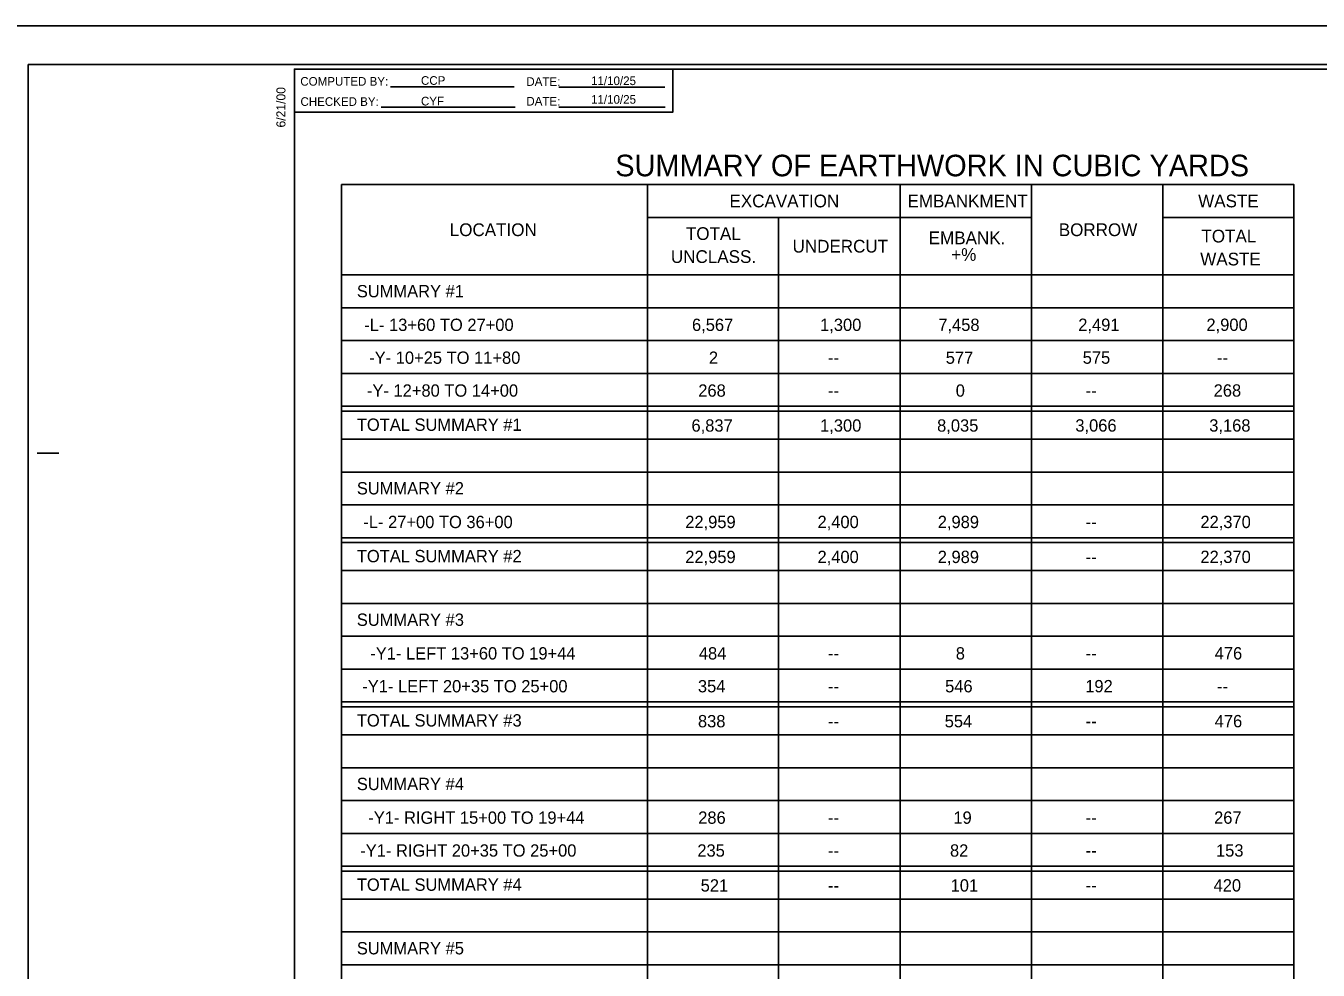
# Model space of a CAD drawing. Extents: x 970719 to 972233, y 692255 to 693335.
# Drawn here: x 971224.1 to 971523.3, y 693116.3 to 693335 of the extents above; entities that cross this region are included whole.
import ezdxf

# ---------------------------------------------------------------- set-up
doc = ezdxf.new("R2010")
doc.units = 0
for name, color, linetype in [('Exist Horizontal Alignment', 7, 'Continuous'), ('Old_Level_1', 7, 'Continuous'), ('Old_Level_2', 7, 'Continuous'), ('Prop EOT', 7, 'Continuous'), ('Prop Horizontal Alignment Direction Label', 7, 'Continuous'), ('Prop Horizontal Alignment Tick Label', 7, 'Continuous')]:
    doc.layers.add(name, color=color, linetype=linetype)

msp = doc.modelspace()

# ---------------------------------------------------------------- linework, layer by layer
at = {"layer": 'Exist Horizontal Alignment'}
for p, q in [((971308.55, 693320.82), (971337.17, 693320.82)), ((971347.49, 693320.76), (971372.05, 693320.76)), ((971306.37, 693316.14), (971337.45, 693316.14)), ((971347.55, 693316.16), (971372.11, 693316.16)), ((971226.73, 693235.98), (971231.73, 693235.98))]:
    msp.add_line(p, q, dxfattribs=at)
for points in [[(971886.29, 693324.98), (971286.29, 693324.98), (971286.29, 692904.98), (971886.29, 692904.98)], [(971286.29, 693324.98), (971373.89, 693324.98), (971373.89, 693314.98), (971286.29, 693314.98)]]:
    msp.add_lwpolyline(points, close=True, dxfattribs=at)
at = {"layer": 'Old_Level_1'}
msp.add_lwpolyline([(971893.09, 693334.98), (971219.49, 693334.98), (971219.49, 692894.98), (971893.09, 692894.98)], close=True, dxfattribs=at)
at = {"layer": 'Prop EOT'}
msp.add_lwpolyline([(971891.29, 693326), (971224.69, 693326), (971224.69, 692903.96), (971891.29, 692903.96)], close=True, dxfattribs=at)
at = {"layer": 'Prop Horizontal Alignment Direction Label'}
msp.add_line((971893.09, 693334.98), (971219.49, 693334.98), dxfattribs=at)
at = {"layer": 'Prop Horizontal Alignment Tick Label'}
for p, q in [((971297.21, 693010.98), (971297.21, 693298.22)), ((971368.03, 693298.22), (971297.21, 693298.22)), ((971368.03, 693010.98), (971368.03, 693290.61)), ((971368.03, 693290.61), (971408.08, 693290.61)), ((971398.41, 693010.98), (971398.41, 693290.61)), ((971426.58, 693010.98), (971426.58, 693290.61)), ((971426.58, 693269.68), (971426.58, 693290.61)), ((971456.97, 693010.98), (971456.97, 693290.61)), ((971487.35, 693010.98), (971487.35, 693290.61)), ((971517.73, 693010.98), (971517.73, 693290.61)), ((971517.73, 693277.29), (971297.21, 693277.29)), ((971297.21, 693269.68), (971426.58, 693269.68)), ((971297.21, 693269.68), (971426.58, 693269.68)), ((971426.58, 693010.98), (971426.58, 693269.68)), ((971426.58, 693269.68), (971517.73, 693269.68)), ((971426.58, 693262.08), (971297.21, 693262.08)), ((971426.58, 693262.08), (971297.21, 693262.08)), ((971517.73, 693262.08), (971426.58, 693262.08)), ((971517.73, 693262.08), (971426.58, 693262.08)), ((971297.21, 693254.47), (971426.58, 693254.47)), ((971426.58, 693254.47), (971517.73, 693254.47)), ((971297.21, 693246.86), (971426.58, 693246.86)), ((971297.21, 693246.86), (971426.58, 693246.86)), ((971426.58, 693246.86), (971297.21, 693246.86)), ((971426.58, 693246.86), (971297.21, 693246.86)), ((971297.21, 693245.75), (971426.58, 693245.75)), ((971517.73, 693246.86), (971426.58, 693246.86)), ((971517.73, 693246.86), (971426.58, 693246.86)), ((971426.58, 693246.86), (971517.73, 693246.86)), ((971426.58, 693246.86), (971517.73, 693246.86)), ((971426.58, 693245.75), (971517.73, 693245.75)), ((971426.58, 693239.25), (971297.21, 693239.25)), ((971517.73, 693239.25), (971426.58, 693239.25)), ((971297.21, 693231.64), (971426.58, 693231.64)), ((971297.21, 693231.64), (971426.58, 693231.64)), ((971426.58, 693231.64), (971517.73, 693231.64)), ((971426.58, 693231.64), (971517.73, 693231.64)), ((971426.58, 693224.03), (971297.21, 693224.03)), ((971426.58, 693224.03), (971297.21, 693224.03)), ((971517.73, 693224.03), (971426.58, 693224.03)), ((971517.73, 693224.03), (971426.58, 693224.03)), ((971297.21, 693216.42), (971426.58, 693216.42)), ((971297.21, 693216.42), (971426.58, 693216.42)), ((971297.21, 693215.32), (971426.58, 693215.32)), ((971426.58, 693216.42), (971517.73, 693216.42)), ((971426.58, 693216.42), (971517.73, 693216.42)), ((971426.58, 693215.32), (971517.73, 693215.32)), ((971426.58, 693208.81), (971297.21, 693208.81)), ((971426.58, 693208.81), (971297.21, 693208.81)), ((971517.73, 693208.81), (971426.58, 693208.81)), ((971517.73, 693208.81), (971426.58, 693208.81)), ((971297.21, 693201.2), (971426.58, 693201.2)), ((971297.21, 693201.2), (971426.58, 693201.2)), ((971426.58, 693201.2), (971517.73, 693201.2)), ((971426.58, 693201.2), (971517.73, 693201.2)), ((971426.58, 693193.59), (971297.21, 693193.59)), ((971426.58, 693193.59), (971297.21, 693193.59)), ((971517.73, 693193.59), (971426.58, 693193.59)), ((971517.73, 693193.59), (971426.58, 693193.59)), ((971426.58, 693185.99), (971297.21, 693185.99)), ((971426.58, 693185.99), (971297.21, 693185.99)), ((971517.73, 693185.99), (971426.58, 693185.99)), ((971517.73, 693185.99), (971426.58, 693185.99)), ((971297.21, 693178.38), (971426.58, 693178.38)), ((971297.21, 693178.38), (971426.58, 693178.38)), ((971297.21, 693177.27), (971426.58, 693177.27)), ((971426.58, 693178.38), (971517.73, 693178.38)), ((971426.58, 693178.38), (971517.73, 693178.38)), ((971426.58, 693177.27), (971517.73, 693177.27)), ((971426.58, 693170.77), (971297.21, 693170.77)), ((971426.58, 693170.77), (971297.21, 693170.77)), ((971517.73, 693170.77), (971426.58, 693170.77)), ((971517.73, 693170.77), (971426.58, 693170.77)), ((971297.21, 693163.16), (971426.58, 693163.16)), ((971297.21, 693163.16), (971426.58, 693163.16)), ((971426.58, 693163.16), (971517.73, 693163.16)), ((971426.58, 693163.16), (971517.73, 693163.16)), ((971426.58, 693155.55), (971297.21, 693155.55)), ((971426.58, 693155.55), (971297.21, 693155.55)), ((971517.73, 693155.55), (971426.58, 693155.55)), ((971517.73, 693155.55), (971426.58, 693155.55)), ((971426.58, 693147.94), (971297.21, 693147.94)), ((971426.58, 693147.94), (971297.21, 693147.94)), ((971517.73, 693147.94), (971426.58, 693147.94)), ((971517.73, 693147.94), (971426.58, 693147.94)), ((971297.21, 693140.33), (971426.58, 693140.33)), ((971297.21, 693140.33), (971426.58, 693140.33)), ((971297.21, 693139.23), (971426.58, 693139.23)), ((971426.58, 693140.33), (971517.73, 693140.33)), ((971426.58, 693140.33), (971517.73, 693140.33)), ((971426.58, 693139.23), (971517.73, 693139.23)), ((971426.58, 693132.72), (971297.21, 693132.72)), ((971426.58, 693132.72), (971297.21, 693132.72)), ((971517.73, 693132.72), (971426.58, 693132.72)), ((971517.73, 693132.72), (971426.58, 693132.72)), ((971297.21, 693125.11), (971426.58, 693125.11)), ((971297.21, 693125.11), (971426.58, 693125.11)), ((971426.58, 693125.11), (971517.73, 693125.11)), ((971426.58, 693125.11), (971517.73, 693125.11)), ((971426.58, 693117.5), (971297.21, 693117.5)), ((971426.58, 693117.5), (971297.21, 693117.5)), ((971517.73, 693117.5), (971426.58, 693117.5)), ((971517.73, 693117.5), (971426.58, 693117.5))]:
    msp.add_line(p, q, dxfattribs=at)
for points in [[(971426.58, 693298.22), (971368.03, 693298.22), (971368.03, 693290.61), (971426.58, 693290.61)], [(971456.97, 693298.22), (971426.58, 693298.22), (971426.58, 693290.61), (971456.97, 693290.61)], [(971456.97, 693298.22), (971487.35, 693298.22), (971487.35, 693277.29), (971456.97, 693277.29)], [(971487.35, 693298.22), (971517.73, 693298.22), (971517.73, 693290.61), (971487.35, 693290.61)]]:
    msp.add_lwpolyline(points, close=True, dxfattribs=at)

# ---------------------------------------------------------------- texts
at = {"layer": 'Exist Horizontal Alignment'}
for s, height, p in [('COMPUTED BY:', 1.9999, (971287.67, 693321.12)), ('DATE:', 2, (971340.01, 693321.08)), ('CHECKED BY:', 1.9999, (971287.71, 693316.44)), ('DATE:', 2, (971340.01, 693316.52)), ('SUMMARY OF EARTHWORK IN CUBIC YARDS', 5, (971360.6, 693300.13))]:
    msp.add_text(s, height=height, dxfattribs=at).set_placement(p)
msp.add_text('6/21/00', height=2.1, rotation=90, dxfattribs=at).set_placement((971284.23, 693311.43))
at = {"layer": 'Old_Level_2'}
for s, p in [('CCP', (971315.61, 693321.32)), ('11/10/25', (971354.99, 693321.26)), ('CYF', (971315.61, 693316.54)), ('11/10/25', (971354.99, 693316.94))]:
    msp.add_text(s, height=2, dxfattribs=at).set_placement(p)
at = {"layer": 'Prop Horizontal Alignment Tick Label'}
for s, p in [('EXCAVATION', (971387.04, 693292.94)), ('EMBANKMENT', (971428.26, 693292.94)), ('WASTE', (971495.55, 693292.94)), ('LOCATION', (971322.27, 693286.28)), ('TOTAL', (971376.95, 693285.39)), ('EMBANK.', (971433.16, 693284.4)), ('BORROW', (971463.28, 693286.28)), ('TOTAL', (971496.31, 693284.81)), ('UNDERCUT', (971401.64, 693282.47)), ('UNCLASS.', (971373.48, 693280.06)), ('+%', (971438.38, 693280.54)), ('WASTE', (971496.03, 693279.49))]:
    msp.add_text(s, height=2.948, rotation=360, dxfattribs=at).set_placement(p)
for s, height, p in [('SUMMARY #1', 2.853, (971300.76, 693272.1)), ('-L- 13+60 TO 27+00', 2.8534, (971302.49, 693264.31)), ('6,567', 2.853, (971378.36, 693264.31)), ('1,300', 2.853, (971408.02, 693264.31)), ('7,458', 2.853, (971435.39, 693264.31)), ('2,491', 2.853, (971467.79, 693264.32)), ('2,900', 2.853, (971497.47, 693264.32)), ('-Y- 10+25 TO 11+80', 2.8534, (971303.62, 693256.7)), ('2', 2.85, (971382.27, 693256.7)), ('--', 2.853, (971409.85, 693256.7)), ('577', 2.853, (971437.11, 693256.7)), ('575', 2.853, (971468.82, 693256.71)), ('--', 2.853, (971499.9, 693256.71)), ('-Y- 12+80 TO 14+00', 2.8534, (971303.1, 693249.09)), ('268', 2.853, (971379.81, 693249.09)), ('0', 2.85, (971439.42, 693249.09)), ('268', 2.853, (971499.14, 693249.1)), ('--', 2.853, (971409.85, 693249.09)), ('--', 2.853, (971469.51, 693249.1)), ('TOTAL SUMMARY #1', 2.8534, (971300.76, 693241.18)), ('6,837', 2.853, (971378.24, 693240.99)), ('1,300', 2.853, (971408.02, 693240.99)), ('8,035', 2.853, (971435.11, 693240.99)), ('3,066', 2.853, (971467.11, 693241)), ('3,168', 2.853, (971498.12, 693241)), ('SUMMARY #2', 2.853, (971300.76, 693226.45)), ('-L- 27+00 TO 36+00', 2.8534, (971302.27, 693218.65)), ('22,959', 2.853, (971376.8, 693218.65)), ('2,400', 2.853, (971407.42, 693218.65)), ('2,989', 2.853, (971435.26, 693218.65)), ('22,370', 2.853, (971496.07, 693218.66)), ('--', 2.853, (971469.51, 693218.66)), ('TOTAL SUMMARY #2', 2.8534, (971300.76, 693210.74)), ('22,959', 2.853, (971376.8, 693210.56)), ('2,400', 2.853, (971407.42, 693210.56)), ('2,989', 2.853, (971435.26, 693210.56)), ('22,370', 2.853, (971496.07, 693210.57)), ('--', 2.853, (971469.51, 693210.57)), ('SUMMARY #3', 2.853, (971300.76, 693196.01)), ('-Y1- LEFT 13+60 TO 19+44', 2.8534, (971303.88, 693188.22)), ('484', 2.853, (971379.94, 693188.22)), ('--', 2.853, (971409.85, 693188.22)), ('8', 2.85, (971439.43, 693188.22)), ('--', 2.853, (971469.51, 693188.23)), ('476', 2.853, (971499.38, 693188.23)), ('-Y1- LEFT 20+35 TO 25+00', 2.8534, (971302.03, 693180.61)), ('354', 2.853, (971379.73, 693180.61)), ('546', 2.853, (971436.96, 693180.61)), ('192', 2.853, (971469.41, 693180.62)), ('--', 2.853, (971409.85, 693180.61)), ('--', 2.853, (971499.9, 693180.62)), ('TOTAL SUMMARY #3', 2.8534, (971300.76, 693172.7)), ('838', 2.853, (971379.74, 693172.51)), ('--', 2.853, (971409.85, 693172.51)), ('554', 2.853, (971436.87, 693172.51)), ('--', 2.853, (971469.51, 693172.52)), ('476', 2.853, (971499.38, 693172.52)), ('SUMMARY #4', 2.853, (971300.76, 693157.97)), ('-Y1- RIGHT 15+00 TO 19+44', 2.8534, (971303.42, 693150.17)), ('286', 2.853, (971379.8, 693150.17)), ('19', 2.853, (971438.88, 693150.17)), ('267', 2.853, (971499.24, 693150.18)), ('--', 2.853, (971409.85, 693150.17)), ('--', 2.853, (971469.51, 693150.18)), ('-Y1- RIGHT 20+35 TO 25+00', 2.8534, (971301.55, 693142.56)), ('235', 2.853, (971379.6, 693142.56)), ('--', 2.853, (971409.85, 693142.56)), ('82', 2.853, (971438.09, 693142.56)), ('--', 2.853, (971469.51, 693142.57)), ('153', 2.853, (971499.68, 693142.57)), ('TOTAL SUMMARY #4', 2.8534, (971300.76, 693134.65)), ('521', 2.853, (971380.37, 693134.47)), ('--', 2.853, (971409.85, 693134.47)), ('101', 2.853, (971438.24, 693134.47)), ('--', 2.853, (971469.51, 693134.48)), ('420', 2.853, (971499.12, 693134.48)), ('SUMMARY #5', 2.853, (971300.76, 693119.92))]:
    msp.add_text(s, height=height, dxfattribs=at).set_placement(p)

doc.saveas('drawing.dxf')
